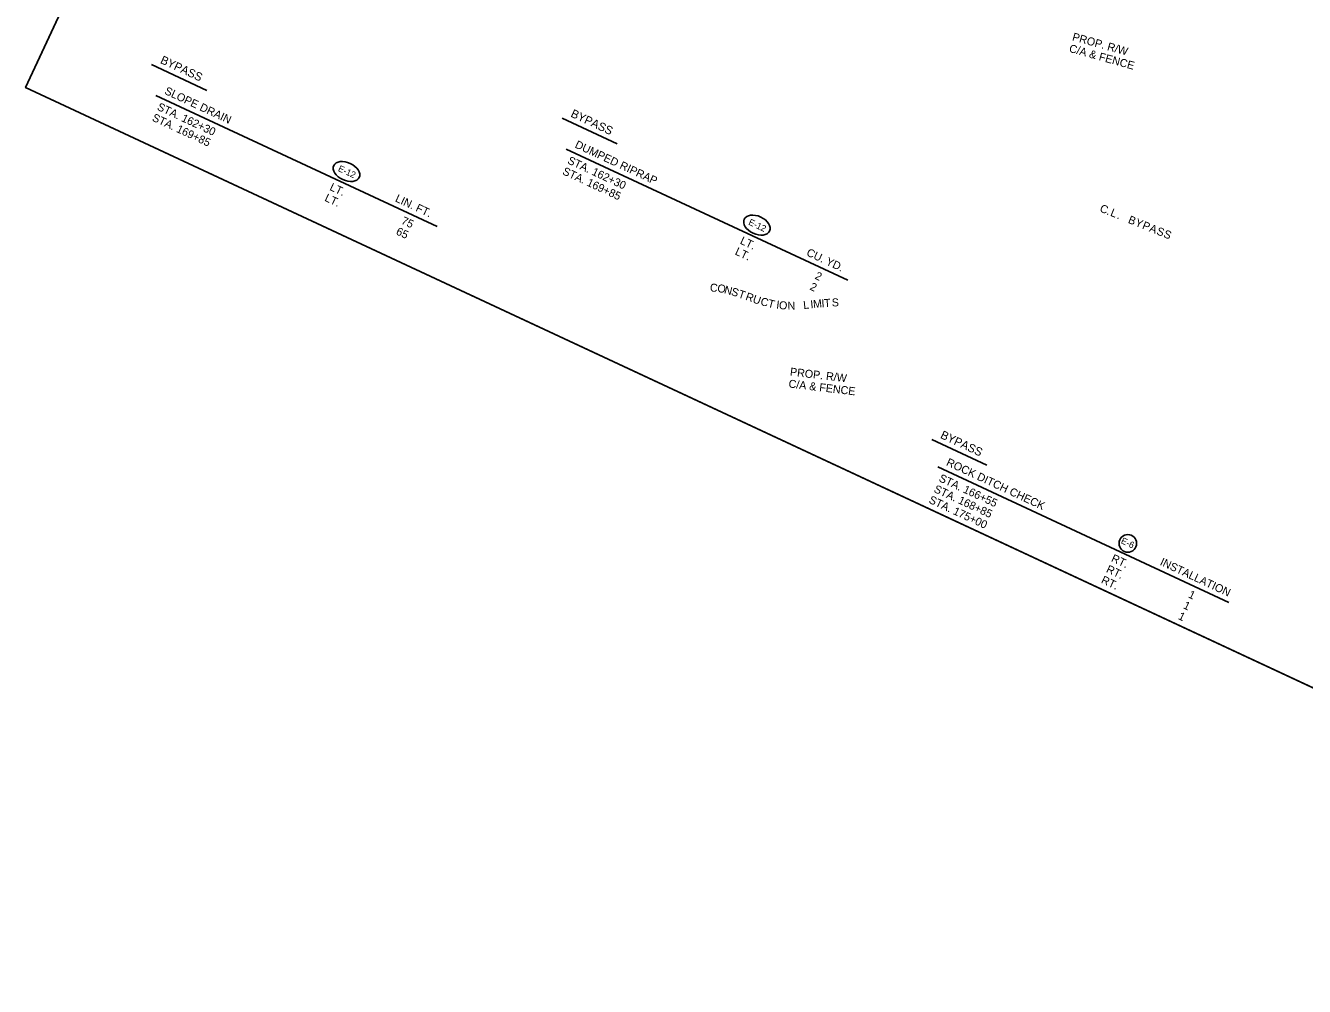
# Model space of a CAD drawing. Extents: x 980231 to 982096, y 1837566 to 1839185.
# Drawn here: x 980231 to 981190, y 1837566 to 1838287 of the extents above; entities that cross this region are included whole.
import ezdxf

# ---------------------------------------------------------------- set-up
doc = ezdxf.new("R2010")
doc.units = 0
for name, color, linetype in [('1', 7, 'Continuous'), ('44', 7, 'Continuous'), ('G-Border-Sheet', 7, 'Continuous'), ('R_Draft', 7, 'Continuous')]:
    doc.layers.add(name, color=color, linetype=linetype)

msp = doc.modelspace()

# ---------------------------------------------------------------- linework, layer by layer
at = {"layer": '1'}
msp.add_circle((981057.47, 1837898.3), 6.61, dxfattribs=at)
for centre in [(980471.55, 1838177.24), (980779.31, 1838137.01)]:
    msp.add_ellipse(centre, major_axis=(9.53, -4.45), ratio=0.638788, dxfattribs=at)
at = {"layer": '44'}
for p, q in [((980325.41, 1838257.38), (980366.72, 1838238.12)), ((980328.63, 1838234.27), (980539.61, 1838135.88)), ((980633.17, 1838217.16), (980674.48, 1838197.9)), ((980636.39, 1838194.04), (980847.38, 1838095.65)), ((980910.39, 1837976.12), (980951.7, 1837956.86)), ((980914.87, 1837955.72), (981133.3, 1837853.86))]:
    msp.add_line(p, q, dxfattribs=at)
at = {"layer": 'G-Border-Sheet'}
for points in [[(981897.02, 1838038.3), (981676.77, 1837565.97), (981495.51, 1837650.49), (980230.88, 1838240.2), (980451.13, 1838712.53), (980461.01, 1838707.92), (980430.47, 1838642.44), (980815.65, 1838462.83), (980846.18, 1838528.31), (981586.46, 1838183.11), (981554.64, 1838114.87), (981865.2, 1837970.06), (981897.02, 1838038.3)], [(981897.02, 1838038.3), (981676.77, 1837565.97), (981495.51, 1837650.49), (980230.88, 1838240.2), (980451.13, 1838712.53), (980461.01, 1838707.92), (980430.47, 1838642.44), (980815.65, 1838462.83), (980846.18, 1838528.31), (981586.46, 1838183.11), (981554.64, 1838114.87), (981865.2, 1837970.06), (981897.02, 1838038.3)], [(981897.02, 1838038.3), (981676.77, 1837565.97), (981495.51, 1837650.49), (980230.88, 1838240.2), (980451.13, 1838712.53), (980461.01, 1838707.92), (980430.52, 1838642.55), (980815.7, 1838462.93), (980846.18, 1838528.31), (981586.46, 1838183.11), (981554.64, 1838114.87), (981865.2, 1837970.06), (981897.02, 1838038.3)], [(981897.02, 1838038.3), (981676.77, 1837565.97), (981495.51, 1837650.49), (980230.88, 1838240.2), (980450.96, 1838712.16), (980460.84, 1838707.56), (980430.52, 1838642.55), (980815.7, 1838462.93), (980846.18, 1838528.31), (981586.46, 1838183.11), (981554.64, 1838114.87), (981865.2, 1837970.06), (981897.02, 1838038.3)], [(981865.2, 1837970.06), (981676.77, 1837565.97), (981404.39, 1837692.98), (980230.88, 1838240.2), (980450.81, 1838711.85), (980460.69, 1838707.24), (980430.52, 1838642.55), (980815.7, 1838462.93), (980846.18, 1838528.31), (981586.46, 1838183.11), (981554.64, 1838114.87)]]:
    msp.add_lwpolyline(points, close=True, dxfattribs=at)

# ---------------------------------------------------------------- texts
at = {"layer": '1'}
for s, rotation, p in [('E-12', 334.99998, (980464.76, 1838177.8)), ('E-12', 334.99998, (980772.52, 1838137.57)), ('E-6 ', 335, (981051.87, 1837898.61))]:
    msp.add_text(s, height=4.8, rotation=rotation, dxfattribs=at).set_placement(p)
at = {"layer": '44'}
for s, height, rotation, p in [('BYPASS', 6.25, 335, (980331.4, 1838258.76)), ('SLOPE DRAIN', 6, 334.99998, (980334.56, 1838235.64)), ('STA. 169+85', 6, 334.99998, (980325.21, 1838215.6)), ('STA. 162+30', 6, 334.99998, (980329, 1838223.71)), ('BYPASS', 6.25, 335, (980639.16, 1838218.54)), ('DUMPED RIPRAP', 6, 334.99998, (980642.32, 1838195.42)), ('STA. 162+30', 6, 334.99998, (980636.76, 1838183.49)), ('STA. 169+85', 6, 334.99998, (980632.97, 1838175.38)), ('LT.', 6, 334.99998, (980458.4, 1838163.54)), ('LT.', 6, 334.99998, (980454.62, 1838155.43)), ('LIN. FT.', 6, 334.99998, (980507.54, 1838154.98)), ('75', 6, 334.99998, (980512.07, 1838138.32)), ('65', 6, 334.99998, (980508.16, 1838130.27)), ('LT.', 6, 334.99998, (980766.16, 1838123.31)), ('LT.', 6, 334.99998, (980762.38, 1838115.2)), ('CU. YD.', 6, 334.99998, (980815.94, 1838114.46)), ('2', 6, 334.99998, (980822.27, 1838096.96)), ('2', 6, 334.99998, (980818.49, 1838088.85)), ('BYPASS', 6.25, 335, (980916.38, 1837977.5)), ('ROCK DITCH CHECK', 6, 335, (980920.8, 1837957.09)), ('STA. 168+85', 6, 334.99998, (980911.46, 1837937.06)), ('STA. 166+55', 6, 334.99998, (980915.24, 1837945.17)), ('STA. 175+00', 6, 334.99998, (980907.68, 1837928.95)), ('RT.', 6, 334.99998, (981044.51, 1837885.05)), ('INSTALLATION', 6, 335, (981081.09, 1837882.35)), ('RT.', 6, 334.99998, (981040.73, 1837876.94)), ('RT.', 6, 334.99998, (981036.95, 1837868.83))]:
    msp.add_text(s, height=height, rotation=rotation, dxfattribs=at).set_placement(p)
at = {"layer": 'R_Draft'}
for s, rotation, p in [('PROP. R/W', 344.42196, (981015.37, 1838275.73)), ('C/A & FENCE', 344.42196, (981012.96, 1838267.06)), ('C', 338.16792, (981035.89, 1838147.36)), ('.', 338.16792, (981041.15, 1838145.26)), ('L', 338.16792, (981043.87, 1838144.17)), ('B', 338.16792, (981057.16, 1838138.84)), ('.', 338.16792, (981048.87, 1838142.16)), ('Y', 338.16792, (981062.42, 1838136.73)), ('P', 338.16792, (981067.77, 1838134.59)), ('A', 338.16792, (981073.04, 1838132.48)), ('S', 338.16792, (981078.47, 1838130.3)), ('S', 338.16792, (981083.74, 1838128.2)), ('C', 353.4758, (980743.79, 1838087.43)), ('O', 353.4758, (980749.42, 1838086.79)), ('N', 345.62977, (980754.37, 1838085.91)), ('S', 341.41138, (980759.46, 1838084.73)), ('T', 341.41138, (980764.84, 1838082.93)), ('R', 340.2771, (980770.28, 1838081.09)), ('U', 340.2771, (980775.61, 1838079.18)), ('C', 345.01278, (980781.55, 1838077.21)), ('T', 345.01278, (980787.03, 1838075.74)), ('I', 353.53961, (980793.64, 1838074.45)), ('O', 353.53961, (980795.61, 1838074.23)), ('N', 2.81264, (980802.4, 1838073.48)), ('L', 5.72096, (980814.35, 1838074.08)), ('I', 5.72096, (980819.71, 1838074.61)), ('M', 5.72096, (980821.69, 1838074.81)), ('I', 4.0832, (980827.92, 1838075.37)), ('T', 4.0832, (980829.9, 1838075.51)), ('S', 2.70763, (980835.59, 1838075.93)), ('PROP. R/W', 353.18192, (980803.87, 1838024.22)), ('C/A & FENCE', 353.18192, (980802.8, 1838015.28)), ('1', 334.99998, (981102.3, 1837857.92)), ('1', 334.99998, (981094.74, 1837841.7)), ('1', 334.99998, (981098.52, 1837849.81))]:
    msp.add_text(s, height=6, rotation=rotation, dxfattribs=at).set_placement(p)

doc.saveas('drawing.dxf')
